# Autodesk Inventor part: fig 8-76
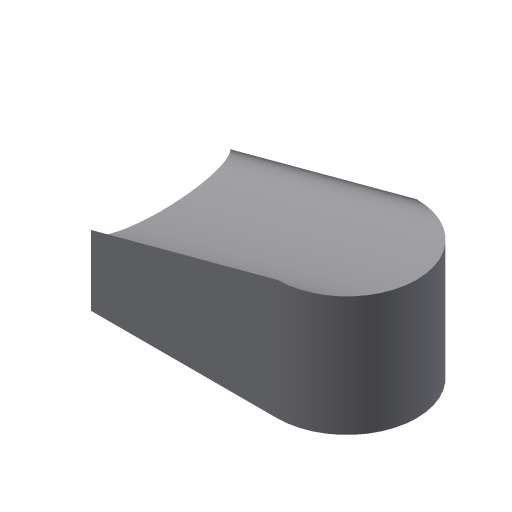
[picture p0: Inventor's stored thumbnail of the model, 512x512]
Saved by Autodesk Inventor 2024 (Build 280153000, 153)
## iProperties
Shininess: 77.0
Length Units: 11269
Angle Units: 11279
Time Units: 11290
Mass Units: 11283
Length Display Precision: 3
Angle Display Precision: 2
Created: 2002-01
Part Number: fig 8-76
Document SubType Name: Modeling
Designer: ***
Density: 1 g/cm^3
Material: Generic
Appearance: Default
Density: 0.0
Volumn: 0.0
Area: 0.0
PropertySet Name: Model Information
Control State: 0
Master: False
Checked Out: False
Author: ***
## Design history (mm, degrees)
sketch "Sketch2"
  geometry: L1 (-25.088, 14.941)-(-25.088, -14.161); L2 (-25.088, -14.161)-(13.729, -14.161); L3 (13.729, 14.941)-(-25.088, 14.941); A1 r 14.551 centre (13.729, 0.39) between (13.729, -14.161) and (13.729, 14.941)
  constraints: 6 end point, 2 point on circle, 2 tangent, 1 centre point, 1 parallel, 1 perpendicular, 1 vertical
extrude "Extrusion2" new body sketch "Sketch2" distance "d6" = 25; taper "d7" = 0 deg
feature "FaceDraft9" dims angle "d15" = 15 deg
body "Solid1"
